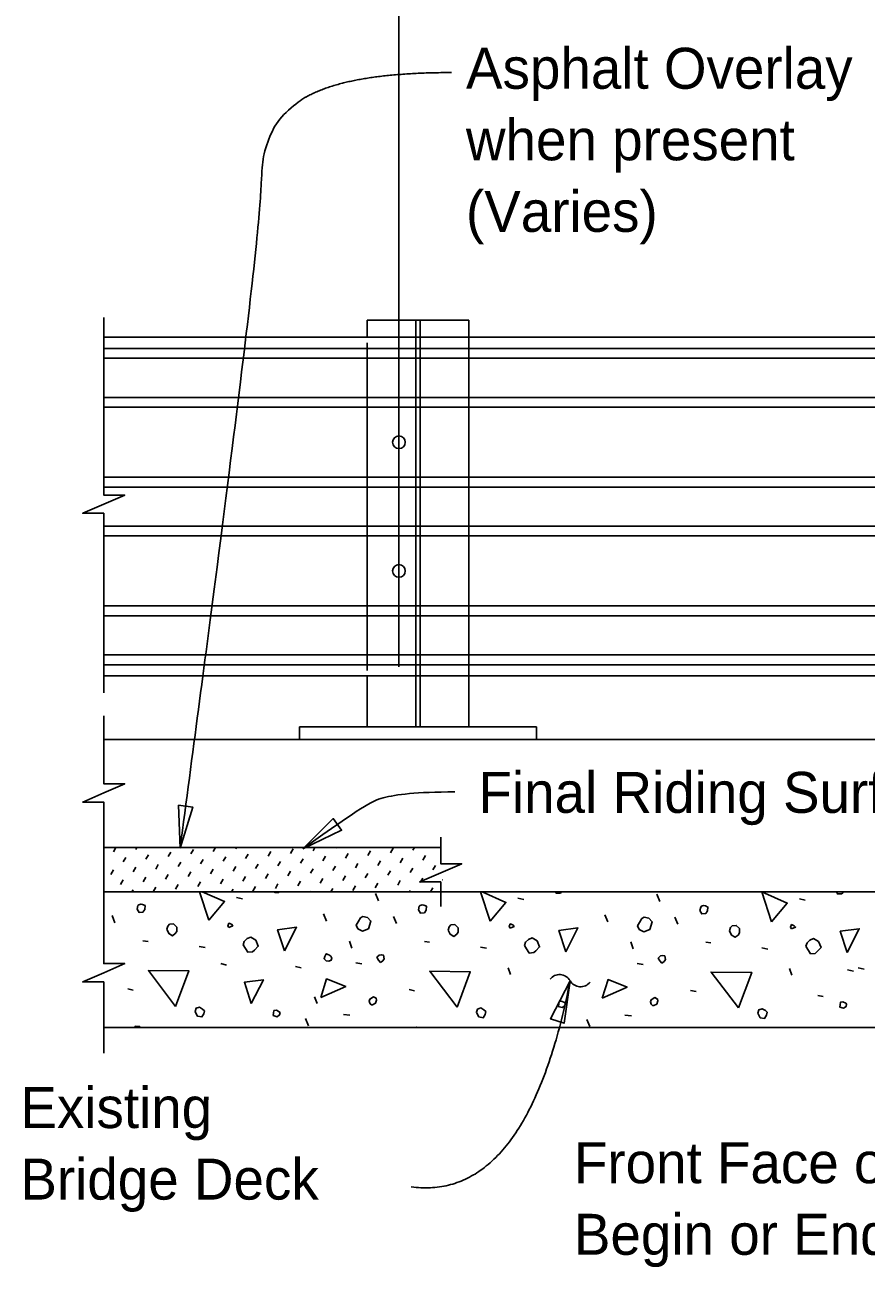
# Model space of a CAD drawing. Extents: x 21587 to 21659.1, y 56116.2 to 56157.3.
# Drawn here: x 21587.27 to 21591.41, y 56132.2 to 56138.32 of the extents above; entities that cross this region are included whole.
import ezdxf

# ---------------------------------------------------------------- set-up
doc = ezdxf.new("R2010")
doc.units = 0
for name, color, linetype in [('AdhocPoint_dp', 7, 'Continuous'), ('Border', 7, 'Continuous'), ('Patterning', 7, 'Continuous'), ('PlotBorder_dp', 7, 'Continuous'), ('SheetBorder_dp', 7, 'Continuous'), ('TextMisc', 7, 'Continuous')]:
    doc.layers.add(name, color=color, linetype=linetype)

msp = doc.modelspace()

# ---------------------------------------------------------------- linework, layer by layer
at = {"layer": 'AdhocPoint_dp'}
for p, q in [((21593.837, 56134.8009), (21587.6633, 56134.8009)), ((21589.3212, 56134.2699), (21587.6633, 56134.2699)), ((21587.6633, 56134.0511), (21593.837, 56134.0511)), ((21587.6633, 56133.3843), (21593.837, 56133.3843))]:
    msp.add_line(p, q, dxfattribs=at)
at = {"layer": 'Border'}
for p, q in [((21588.9596, 56136.8635), (21589.4596, 56136.8635)), ((21588.9596, 56136.8635), (21588.9596, 56136.7802)), ((21589.4596, 56136.8635), (21589.4596, 56136.7802)), ((21599.7592, 56136.7801), (21587.6633, 56136.7801)), ((21587.6633, 56136.7246), (21599.7592, 56136.7246)), ((21587.6633, 56136.6764), (21599.7592, 56136.6764)), ((21587.6633, 56136.4835), (21599.7592, 56136.4835)), ((21587.6633, 56136.4353), (21599.7592, 56136.4353)), ((21587.6633, 56136.0914), (21599.7592, 56136.0914)), ((21587.6633, 56136.0431), (21599.7592, 56136.0431)), ((21587.6633, 56135.8503), (21599.7592, 56135.8503)), ((21587.6633, 56135.8022), (21599.7592, 56135.8022)), ((21587.6633, 56135.4582), (21599.7592, 56135.4582)), ((21587.6633, 56135.41), (21599.7592, 56135.41)), ((21587.6633, 56135.2172), (21599.7592, 56135.2172)), ((21587.6633, 56135.169), (21599.7592, 56135.169)), ((21599.7592, 56135.1134), (21587.6633, 56135.1134)), ((21588.9596, 56135.1135), (21588.9596, 56134.8635)), ((21589.4596, 56135.1134), (21589.4596, 56134.8635)), ((21588.6263, 56134.8635), (21589.7929, 56134.8635)), ((21588.6263, 56134.801), (21588.6263, 56134.8635)), ((21588.9596, 56134.8635), (21589.4596, 56134.8635)), ((21589.7929, 56134.8635), (21589.7929, 56134.801)), ((21588.6263, 56134.801), (21589.7929, 56134.801))]:
    msp.add_line(p, q, dxfattribs=at)
for centre in [(21589.1159, 56136.2634), (21589.1159, 56135.6303)]:
    msp.add_circle(centre, 0.0312, dxfattribs=at)
at = {"layer": 'Patterning'}
for p, q in [((21589.1992, 56134.8635), (21589.1992, 56136.8635)), ((21589.22, 56134.8635), (21589.22, 56136.8635)), ((21588.9596, 56136.7516), (21588.9596, 56135.1398)), ((21589.4596, 56136.7801), (21589.4596, 56135.1134))]:
    msp.add_line(p, q, dxfattribs=at)
at = {"layer": 'PlotBorder_dp'}
msp.add_line((21589.1159, 56135.1581), (21589.1159, 56143.3113), dxfattribs=at)
for points in [[(21587.6633, 56135.0304), (21587.6633, 56135.9136), (21587.5599, 56135.9136), (21587.6633, 56135.9586), (21587.7666, 56136.0036), (21587.6633, 56136.0036), (21587.6633, 56136.8766)], [(21587.6633, 56134.023), (21587.6633, 56134.4931), (21587.5599, 56134.4931), (21587.6633, 56134.5381), (21587.7666, 56134.5831), (21587.6633, 56134.5831), (21587.6633, 56134.9176)], [(21589.3213, 56133.979), (21589.3213, 56134.0999), (21589.2179, 56134.0999), (21589.3213, 56134.1449), (21589.4246, 56134.1899), (21589.3213, 56134.1899), (21589.3213, 56134.3205)], [(21587.6633, 56133.2579), (21587.6633, 56133.6085), (21587.5599, 56133.6085), (21587.6633, 56133.6535), (21587.7666, 56133.6985), (21587.6633, 56133.6985), (21587.6633, 56134.023)]]:
    msp.add_lwpolyline(points, dxfattribs=at)
for points in [[(21588.0386, 56134.2665), (21588.1011, 56134.4682), (21588.0312, 56134.4775)], [(21588.6428, 56134.2633), (21588.8333, 56134.3544), (21588.7927, 56134.4121)], [(21589.9584, 56133.6142), (21589.928, 56133.4052), (21589.8608, 56133.4269)]]:
    msp.add_lwpolyline(points, close=True, dxfattribs=at)
for centre, start, end in [((21589.9061, 56133.5845), 30.00813, 141.73535), ((21590.0093, 56133.6441), 210.00813, 321.73535)]:
    msp.add_arc(centre, 0.0596, start, end, dxfattribs=at)
for points, degree in [([(21589.3746, 56138.082), (21588.8608, 56138.082), (21588.4383, 56137.8307), (21588.4383, 56137.2595), (21588.0386, 56134.2665)], 2), ([(21589.3913, 56134.5436), (21589.1979, 56134.5415), (21589.0095, 56134.5211), (21588.9381, 56134.4713), (21588.6427, 56134.2634)], 3), ([(21589.9584, 56133.6142), (21589.743, 56132.5258), (21589.1766, 56132.5995)], 2)]:
    msp.add_open_spline(points, degree=degree, dxfattribs=at)
at = {"layer": 'TextMisc'}
for p, q in [((21587.7102, 56134.2474), (21587.7231, 56134.2698)), ((21587.8208, 56134.2604), (21587.8263, 56134.2699)), ((21587.9803, 56134.2245), (21587.9932, 56134.2469)), ((21588.0909, 56134.2375), (21588.1039, 56134.2599)), ((21588.2015, 56134.2504), (21588.2128, 56134.2699)), ((21588.3122, 56134.2634), (21588.3159, 56134.2699)), ((21588.4716, 56134.2275), (21588.4846, 56134.2499)), ((21588.5823, 56134.2405), (21588.5952, 56134.2629)), ((21588.6929, 56134.2535), (21588.7024, 56134.2699)), ((21588.8035, 56134.2664), (21588.8055, 56134.2699)), ((21588.963, 56134.2306), (21588.976, 56134.253)), ((21589.0736, 56134.2435), (21589.0866, 56134.2659)), ((21589.1843, 56134.2565), (21589.192, 56134.2699)), ((21589.2949, 56134.2695), (21589.2952, 56134.2699)), ((21587.759, 56134.1986), (21587.772, 56134.221)), ((21587.8696, 56134.2116), (21587.8826, 56134.234)), ((21587.9185, 56134.1627), (21587.9314, 56134.1851)), ((21588.0291, 56134.1757), (21588.0421, 56134.1981)), ((21588.1397, 56134.1887), (21588.1527, 56134.211)), ((21588.2504, 56134.2016), (21588.2633, 56134.224)), ((21588.361, 56134.2146), (21588.374, 56134.237)), ((21588.4098, 56134.1657), (21588.4228, 56134.1881)), ((21588.5205, 56134.1787), (21588.5334, 56134.2011)), ((21588.6311, 56134.1917), (21588.6441, 56134.2141)), ((21588.7417, 56134.2046), (21588.7547, 56134.227)), ((21588.8524, 56134.2176), (21588.8653, 56134.24)), ((21588.9012, 56134.1688), (21588.9142, 56134.1912)), ((21589.0118, 56134.1817), (21589.0248, 56134.2041)), ((21589.1225, 56134.1947), (21589.1354, 56134.2171)), ((21589.2331, 56134.2077), (21589.2461, 56134.23)), ((21589.2819, 56134.1588), (21589.2949, 56134.1812)), ((21587.6972, 56134.1368), (21587.7102, 56134.1592)), ((21587.8078, 56134.1498), (21587.8208, 56134.1722)), ((21587.8567, 56134.1009), (21587.8696, 56134.1233)), ((21587.9673, 56134.1139), (21587.9803, 56134.1363)), ((21588.0779, 56134.1269), (21588.0909, 56134.1492)), ((21588.1886, 56134.1398), (21588.2015, 56134.1622)), ((21588.2992, 56134.1528), (21588.3122, 56134.1752)), ((21588.348, 56134.1039), (21588.361, 56134.1263)), ((21588.4587, 56134.1169), (21588.4716, 56134.1393)), ((21588.5693, 56134.1299), (21588.5823, 56134.1523)), ((21588.6799, 56134.1428), (21588.6929, 56134.1652)), ((21588.7906, 56134.1558), (21588.8035, 56134.1782)), ((21588.8394, 56134.107), (21588.8524, 56134.1294)), ((21588.95, 56134.1199), (21588.963, 56134.1423)), ((21589.0607, 56134.1329), (21589.0736, 56134.1553)), ((21589.1713, 56134.1459), (21589.1843, 56134.1682)), ((21589.2201, 56134.097), (21589.2331, 56134.1194)), ((21587.746, 56134.088), (21587.759, 56134.1104)), ((21587.8017, 56134.0509), (21587.8078, 56134.0615)), ((21587.9055, 56134.0521), (21587.9185, 56134.0745)), ((21588.0161, 56134.0651), (21588.0291, 56134.0874)), ((21588.1268, 56134.078), (21588.1397, 56134.1004)), ((21588.2374, 56134.091), (21588.2504, 56134.1134)), ((21588.2913, 56134.0509), (21588.2992, 56134.0645)), ((21588.3969, 56134.0551), (21588.4098, 56134.0775)), ((21588.5075, 56134.0681), (21588.5205, 56134.0905)), ((21588.6181, 56134.081), (21588.6311, 56134.1034)), ((21588.7288, 56134.094), (21588.7417, 56134.1164)), ((21588.7809, 56134.0509), (21588.7906, 56134.0676)), ((21588.8882, 56134.0581), (21588.9012, 56134.0805)), ((21588.9989, 56134.0711), (21589.0118, 56134.0935)), ((21589.1095, 56134.0841), (21589.1225, 56134.1065)), ((21589.2706, 56134.0509), (21589.2819, 56134.0706)), ((21589.3308, 56134.11), (21589.3309, 56134.1102)), ((21588.1882, 56134.0509), (21588.1886, 56134.0516)), ((21588.3168, 56134.0238), (21588.3451, 56134.0167)), ((21588.6778, 56134.0509), (21588.6799, 56134.0546)), ((21589.0151, 56134.0079), (21589.001, 56134.0432)), ((21589.1674, 56134.0509), (21589.1713, 56134.0576)), ((21589.7015, 56134.0203), (21589.7298, 56134.0132)), ((21590.3998, 56134.0043), (21590.3856, 56134.0397)), ((21591.0862, 56134.0167), (21591.1145, 56134.0096)), ((21588.7588, 56133.9071), (21588.7446, 56133.9425)), ((21590.1435, 56133.9036), (21590.1293, 56133.9389)), ((21587.7182, 56133.8989), (21587.7041, 56133.9343)), ((21589.1029, 56133.8954), (21589.0887, 56133.9307)), ((21590.4875, 56133.8918), (21590.4734, 56133.9272)), ((21587.8561, 56133.8105), (21587.8808, 56133.807)), ((21588.1319, 56133.7822), (21588.1619, 56133.7769)), ((21588.8843, 56133.7745), (21588.8719, 56133.8081)), ((21589.2408, 56133.807), (21589.2655, 56133.8034)), ((21589.5165, 56133.7787), (21589.5466, 56133.7734)), ((21590.269, 56133.771), (21590.2566, 56133.8046)), ((21590.6254, 56133.8034), (21590.6502, 56133.7999)), ((21590.9012, 56133.7752), (21590.9313, 56133.7699)), ((21588.2388, 56133.6983), (21588.2671, 56133.6913)), ((21588.9031, 56133.7027), (21588.9332, 56133.6974)), ((21590.2878, 56133.6991), (21590.3178, 56133.6938)), ((21588.6068, 56133.6844), (21588.635, 56133.6773)), ((21589.665, 56133.6443), (21589.6526, 56133.6779)), ((21591.0497, 56133.6408), (21591.0373, 56133.6744)), ((21591.3237, 56133.6673), (21591.352, 56133.6603)), ((21591.3761, 56133.6773), (21591.4044, 56133.6702)), ((21587.7818, 56133.5736), (21587.8083, 56133.5683)), ((21589.1665, 56133.5701), (21589.193, 56133.5648)), ((21588.7128, 56133.5018), (21588.7004, 56133.5354)), ((21590.5512, 56133.5666), (21590.5777, 56133.5613)), ((21591.177, 56133.5418), (21591.2035, 56133.5365)), ((21588.843, 56133.4481), (21588.8748, 56133.4446)), ((21588.6704, 56133.3922), (21588.6563, 56133.4275)), ((21590.0551, 56133.3886), (21590.0409, 56133.424)), ((21590.2277, 56133.4446), (21590.2595, 56133.4411))]:
    msp.add_line(p, q, dxfattribs=at)
for points in [[(21588.1796, 56133.9113), (21588.1341, 56134.0509)], [(21588.148, 56134.0509), (21588.2574, 56134.0032), (21588.1796, 56133.9113)], [(21588.5032, 56134.0509), (21588.5042, 56134.0485), (21588.5018, 56134.0509)], [(21588.5042, 56134.0485), (21588.5254, 56134.0485), (21588.5278, 56134.0509)], [(21589.5643, 56133.9077), (21589.5177, 56134.0509)], [(21589.5246, 56134.0509), (21589.642, 56133.9997), (21589.5643, 56133.9077)], [(21589.8864, 56134.0509), (21589.8889, 56134.045), (21589.8854, 56134.0485)], [(21589.8889, 56134.045), (21589.9101, 56134.045), (21589.9161, 56134.0509)], [(21590.9489, 56133.9042), (21590.9012, 56134.0509), (21591.0267, 56133.9961), (21590.9489, 56133.9042)], [(21591.2695, 56134.0509), (21591.2736, 56134.0415), (21591.27, 56134.045)], [(21591.2736, 56134.0415), (21591.2948, 56134.0415), (21591.3043, 56134.0509)], [(21587.8278, 56133.9661), (21587.8366, 56133.9502), (21587.8561, 56133.9519), (21587.8649, 56133.9643), (21587.8667, 56133.9838), (21587.8543, 56133.9891), (21587.8455, 56133.9908), (21587.8349, 56133.9873), (21587.8313, 56133.9838), (21587.8278, 56133.9661)], [(21589.2125, 56133.9625), (21589.2213, 56133.9466), (21589.2408, 56133.9484), (21589.2496, 56133.9608), (21589.2514, 56133.9802), (21589.239, 56133.9855), (21589.2302, 56133.9873), (21589.2195, 56133.9838), (21589.216, 56133.9802), (21589.2125, 56133.9625)], [(21590.5971, 56133.959), (21590.606, 56133.9431), (21590.6254, 56133.9449), (21590.6343, 56133.9572), (21590.636, 56133.9767), (21590.6237, 56133.982), (21590.6148, 56133.9838), (21590.6042, 56133.9802), (21590.6007, 56133.9767), (21590.5971, 56133.959)], [(21587.9728, 56133.8671), (21587.9834, 56133.8459), (21588.001, 56133.8353), (21588.0152, 56133.8459), (21588.0222, 56133.8565), (21588.0222, 56133.8777), (21588.0063, 56133.8936), (21587.9869, 56133.8918), (21587.9781, 56133.883), (21587.9728, 56133.8671)], [(21588.2786, 56133.8759), (21588.298, 56133.8848), (21588.291, 56133.8918), (21588.2786, 56133.8971), (21588.2733, 56133.8848), (21588.2786, 56133.8759)], [(21588.552, 56133.7604), (21588.5184, 56133.8647), (21588.6121, 56133.8771), (21588.552, 56133.7604)], [(21588.9126, 56133.87), (21588.9356, 56133.8576), (21588.9656, 56133.87), (21588.978, 56133.9071), (21588.9603, 56133.9248), (21588.9373, 56133.9301), (21588.9267, 56133.923), (21588.9143, 56133.9036), (21588.9055, 56133.8877), (21588.9126, 56133.87)], [(21589.3574, 56133.8635), (21589.368, 56133.8423), (21589.3857, 56133.8317), (21589.3999, 56133.8423), (21589.4069, 56133.8529), (21589.4069, 56133.8742), (21589.391, 56133.8901), (21589.3716, 56133.8883), (21589.3627, 56133.8795), (21589.3574, 56133.8635)], [(21589.6633, 56133.8724), (21589.6827, 56133.8812), (21589.6756, 56133.8883), (21589.6633, 56133.8936), (21589.6579, 56133.8812), (21589.6633, 56133.8724)], [(21590.2973, 56133.8665), (21590.3202, 56133.8541), (21590.3503, 56133.8665), (21590.3627, 56133.9036), (21590.345, 56133.9213), (21590.322, 56133.9266), (21590.3114, 56133.9195), (21590.299, 56133.9), (21590.2902, 56133.8841), (21590.2973, 56133.8665)], [(21590.7421, 56133.86), (21590.7527, 56133.8388), (21590.7704, 56133.8282), (21590.7845, 56133.8388), (21590.7916, 56133.8494), (21590.7916, 56133.8706), (21590.7757, 56133.8865), (21590.7562, 56133.8848), (21590.7474, 56133.8759), (21590.7421, 56133.86)], [(21591.0479, 56133.8689), (21591.0674, 56133.8777), (21591.0603, 56133.8848), (21591.0479, 56133.8901), (21591.0426, 56133.8777), (21591.0479, 56133.8689)], [(21588.3493, 56133.7911), (21588.3723, 56133.7539), (21588.3952, 56133.7557), (21588.4041, 56133.7646), (21588.4235, 56133.784), (21588.4112, 56133.814), (21588.3864, 56133.8282), (21588.3687, 56133.8211), (21588.3546, 56133.807), (21588.3493, 56133.7911)], [(21589.734, 56133.7875), (21589.7569, 56133.7504), (21589.7799, 56133.7522), (21589.7888, 56133.761), (21589.8082, 56133.7805), (21589.7958, 56133.8105), (21589.7711, 56133.8247), (21589.7534, 56133.8176), (21589.7393, 56133.8034), (21589.734, 56133.7875)], [(21589.9366, 56133.7569), (21589.903, 56133.8612), (21589.9967, 56133.8735), (21589.9366, 56133.7569)], [(21591.1186, 56133.784), (21591.1416, 56133.7469), (21591.1646, 56133.7486), (21591.1734, 56133.7575), (21591.1929, 56133.7769), (21591.1805, 56133.807), (21591.1558, 56133.8211), (21591.1381, 56133.814), (21591.1239, 56133.7999), (21591.1186, 56133.784)], [(21591.3213, 56133.7533), (21591.2877, 56133.8576), (21591.3814, 56133.87), (21591.3213, 56133.7533)], [(21588.7577, 56133.7114), (21588.7701, 56133.7096), (21588.7824, 56133.7149), (21588.786, 56133.7256), (21588.7807, 56133.7344), (21588.7701, 56133.7415), (21588.7577, 56133.7468), (21588.7506, 56133.7326), (21588.7471, 56133.722), (21588.7577, 56133.7114)], [(21589.0145, 56133.7151), (21589.0251, 56133.7044), (21589.0357, 56133.7115), (21589.0428, 56133.7221), (21589.0392, 56133.7398), (21589.0304, 56133.7416), (21589.018, 56133.7398), (21589.0074, 56133.7292), (21589.0145, 56133.7151)], [(21590.3992, 56133.7115), (21590.4098, 56133.7009), (21590.4204, 56133.708), (21590.4274, 56133.7186), (21590.4239, 56133.7363), (21590.4151, 56133.738), (21590.4027, 56133.7363), (21590.3921, 56133.7257), (21590.3992, 56133.7115)], [(21588.0169, 56133.487), (21587.8826, 56133.6638), (21588.0824, 56133.662), (21588.0169, 56133.487)], [(21589.4016, 56133.4835), (21589.2673, 56133.6603), (21589.467, 56133.6585), (21589.4016, 56133.4835)], [(21590.7863, 56133.4799), (21590.652, 56133.6567), (21590.8517, 56133.655), (21590.7863, 56133.4799)], [(21588.3887, 56133.5022), (21588.3551, 56133.6065), (21588.4488, 56133.6188), (21588.3887, 56133.5022)], [(21588.7316, 56133.5312), (21588.7599, 56133.6231), (21588.8536, 56133.586), (21588.7316, 56133.5312)], [(21590.1163, 56133.5277), (21590.1446, 56133.6196), (21590.2383, 56133.5825), (21590.1163, 56133.5277)], [(21588.9791, 56133.4959), (21588.9862, 56133.4959), (21589.0003, 56133.5029), (21589.0056, 56133.5188), (21589.0039, 56133.5277), (21588.9897, 56133.5347), (21588.9721, 56133.5241), (21588.9685, 56133.5135), (21588.9721, 56133.5029), (21588.9791, 56133.4959)], [(21589.9001, 56133.487), (21589.9196, 56133.4817), (21589.932, 56133.4905), (21589.9337, 56133.5029), (21589.9302, 56133.5065), (21589.916, 56133.5135), (21589.9037, 56133.5118), (21589.9019, 56133.4994), (21589.9001, 56133.487)], [(21590.3638, 56133.4923), (21590.3709, 56133.4923), (21590.385, 56133.4994), (21590.3903, 56133.5153), (21590.3886, 56133.5241), (21590.3744, 56133.5312), (21590.3567, 56133.5206), (21590.3532, 56133.51), (21590.3567, 56133.4994), (21590.3638, 56133.4923)], [(21591.2848, 56133.4835), (21591.3043, 56133.4782), (21591.3166, 56133.487), (21591.3184, 56133.4994), (21591.3149, 56133.5029), (21591.3007, 56133.51), (21591.2883, 56133.5082), (21591.2866, 56133.4959), (21591.2848, 56133.4835)], [(21588.1159, 56133.4552), (21588.1248, 56133.4393), (21588.146, 56133.4357), (21588.1548, 56133.4517), (21588.1584, 56133.4658), (21588.1495, 56133.4746), (21588.1336, 56133.4835), (21588.1177, 56133.4782), (21588.1124, 56133.4623), (21588.1159, 56133.4552)], [(21588.4968, 56133.4422), (21588.5163, 56133.4369), (21588.5286, 56133.4457), (21588.5304, 56133.4581), (21588.5269, 56133.4617), (21588.5127, 56133.4687), (21588.5003, 56133.467), (21588.4986, 56133.4546), (21588.4968, 56133.4422)], [(21589.5006, 56133.4517), (21589.5095, 56133.4357), (21589.5307, 56133.4322), (21589.5395, 56133.4481), (21589.543, 56133.4623), (21589.5342, 56133.4711), (21589.5183, 56133.4799), (21589.5024, 56133.4746), (21589.4971, 56133.4587), (21589.5006, 56133.4517)], [(21590.8853, 56133.4481), (21590.8941, 56133.4322), (21590.9153, 56133.4287), (21590.9242, 56133.4446), (21590.9277, 56133.4587), (21590.9189, 56133.4676), (21590.903, 56133.4764), (21590.8871, 56133.4711), (21590.8818, 56133.4552), (21590.8853, 56133.4481)], [(21587.8412, 56133.3843), (21587.8402, 56133.388), (21587.8172, 56133.3898), (21587.8154, 56133.3843)], [(21589.2249, 56133.3843), (21589.2248, 56133.3845), (21589.2019, 56133.3862), (21589.2012, 56133.3843)]]:
    msp.add_lwpolyline(points, dxfattribs=at)

# ---------------------------------------------------------------- texts
at = {"layer": 'PlotBorder_dp'}
for s, p in [('Asphalt Overlay', (21589.4456, 56138.0025)), ('when present', (21589.4456, 56137.6505)), ('(Varies)', (21589.4456, 56137.2985)), ('Existing ', (21587.2526, 56132.8891)), ('Front Face of Backwall &', (21589.9768, 56132.6176)), ('Bridge Deck', (21587.2526, 56132.5371)), ('Begin or End Bridge', (21589.9768, 56132.2656))]:
    msp.add_text(s, height=0.2016, dxfattribs=at).set_placement(p)
at = {"layer": 'SheetBorder_dp'}
msp.add_text('Final Riding Surface', height=0.2016, dxfattribs=at).set_placement((21589.5074, 56134.4399))

doc.saveas('drawing.dxf')
